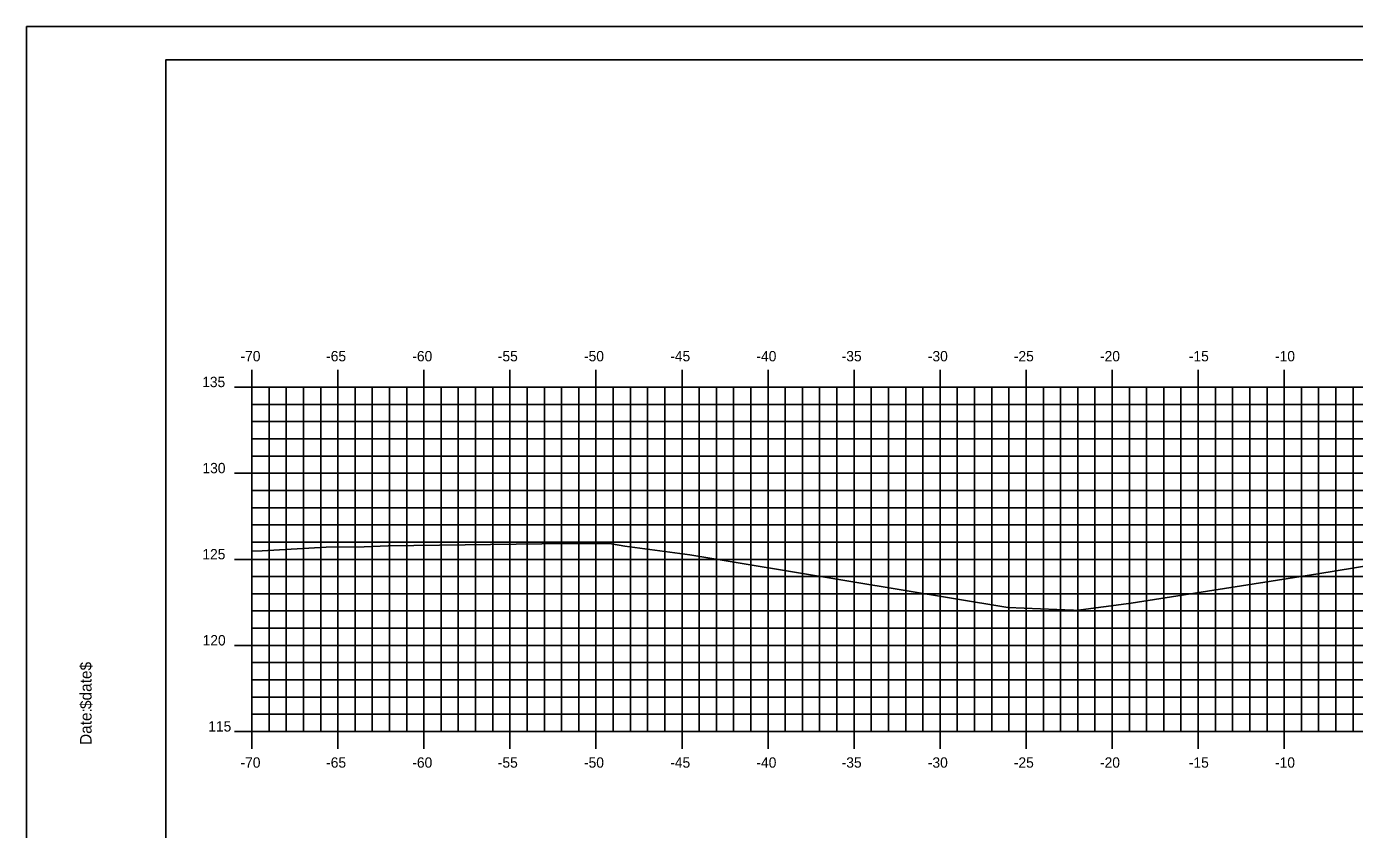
# Model space of a CAD drawing. Extents: x 851738 to 851910, y 365624 to 365734.
# Drawn here: x 851738.4 to 851815.6, y 365687.3 to 365734 of the extents above; entities that cross this region are included whole.
import ezdxf

# ---------------------------------------------------------------- set-up
doc = ezdxf.new("R2010")
doc.units = 0
for name, color, linetype in [('BORDER', 7, 'Continuous'), ('H_V ANNOTATION', 7, 'Continuous'), ('M_Roadway_Centerline', 7, 'Continuous'), ('MAJOR', 7, 'Continuous'), ('MINOR', 7, 'Continuous'), ('PLOT BOUNDARY', 7, 'Continuous'), ('S_Roadway_Centerline', 7, 'Continuous')]:
    doc.layers.add(name, color=color, linetype=linetype)

msp = doc.modelspace()

# ---------------------------------------------------------------- linework, layer by layer
at = {"layer": 'BORDER'}
msp.add_lwpolyline([(851746.522, 365627.027), (851906.522, 365627.027), (851906.522, 365732.027), (851746.522, 365732.027)], close=True, dxfattribs=at)
at = {"layer": 'MAJOR'}
for p, q in [((851751.522, 365714.029), (851751.522, 365713.027)), ((851756.522, 365714.029), (851756.522, 365713.027)), ((851761.522, 365714.029), (851761.522, 365713.027)), ((851766.522, 365714.029), (851766.522, 365713.027)), ((851771.522, 365714.029), (851771.522, 365713.027)), ((851776.522, 365714.029), (851776.522, 365713.027)), ((851781.522, 365714.029), (851781.522, 365713.027)), ((851786.522, 365714.029), (851786.522, 365713.027)), ((851791.522, 365714.029), (851791.522, 365713.027)), ((851796.522, 365714.029), (851796.522, 365713.027)), ((851801.522, 365714.029), (851801.522, 365713.027)), ((851806.522, 365714.029), (851806.522, 365713.027)), ((851811.522, 365714.029), (851811.522, 365713.027)), ((851750.52, 365713.027), (851751.522, 365713.027)), ((851751.522, 365713.027), (851891.522, 365713.027)), ((851751.522, 365693.027), (851751.522, 365713.027)), ((851751.522, 365693.027), (851751.522, 365713.027)), ((851751.522, 365713.027), (851891.522, 365713.027)), ((851756.522, 365693.027), (851756.522, 365713.027)), ((851761.522, 365693.027), (851761.522, 365713.027)), ((851766.522, 365693.027), (851766.522, 365713.027)), ((851771.522, 365693.027), (851771.522, 365713.027)), ((851776.522, 365693.027), (851776.522, 365713.027)), ((851781.522, 365693.027), (851781.522, 365713.027)), ((851786.522, 365693.027), (851786.522, 365713.027)), ((851791.522, 365693.027), (851791.522, 365713.027)), ((851796.522, 365693.027), (851796.522, 365713.027)), ((851801.522, 365693.027), (851801.522, 365713.027)), ((851806.522, 365693.027), (851806.522, 365713.027)), ((851811.522, 365693.027), (851811.522, 365713.027)), ((851750.52, 365708.027), (851751.522, 365708.027)), ((851751.522, 365708.027), (851891.522, 365708.027)), ((851750.52, 365703.027), (851751.522, 365703.027)), ((851751.522, 365703.027), (851891.522, 365703.027)), ((851750.52, 365698.027), (851751.522, 365698.027)), ((851751.522, 365698.027), (851891.522, 365698.027)), ((851750.52, 365693.027), (851751.522, 365693.027)), ((851751.522, 365693.027), (851891.522, 365693.027)), ((851751.522, 365693.027), (851891.522, 365693.027)), ((851751.522, 365692.025), (851751.522, 365693.027)), ((851756.522, 365692.025), (851756.522, 365693.027)), ((851761.522, 365692.025), (851761.522, 365693.027)), ((851766.522, 365692.025), (851766.522, 365693.027)), ((851771.522, 365692.025), (851771.522, 365693.027)), ((851776.522, 365692.025), (851776.522, 365693.027)), ((851781.522, 365692.025), (851781.522, 365693.027)), ((851786.522, 365692.025), (851786.522, 365693.027)), ((851791.522, 365692.025), (851791.522, 365693.027)), ((851796.522, 365692.025), (851796.522, 365693.027)), ((851801.522, 365692.025), (851801.522, 365693.027)), ((851806.522, 365692.025), (851806.522, 365693.027)), ((851811.522, 365692.025), (851811.522, 365693.027))]:
    msp.add_line(p, q, dxfattribs=at)
at = {"layer": 'MINOR'}
for p, q in [((851752.522, 365693.027), (851752.522, 365713.027)), ((851753.522, 365693.027), (851753.522, 365713.027)), ((851754.522, 365693.027), (851754.522, 365713.027)), ((851755.522, 365693.027), (851755.522, 365713.027)), ((851757.522, 365693.027), (851757.522, 365713.027)), ((851758.522, 365693.027), (851758.522, 365713.027)), ((851759.522, 365693.027), (851759.522, 365713.027)), ((851760.522, 365693.027), (851760.522, 365713.027)), ((851762.522, 365693.027), (851762.522, 365713.027)), ((851763.522, 365693.027), (851763.522, 365713.027)), ((851764.522, 365693.027), (851764.522, 365713.027)), ((851765.522, 365693.027), (851765.522, 365713.027)), ((851767.522, 365693.027), (851767.522, 365713.027)), ((851768.522, 365693.027), (851768.522, 365713.027)), ((851769.522, 365693.027), (851769.522, 365713.027)), ((851770.522, 365693.027), (851770.522, 365713.027)), ((851772.522, 365693.027), (851772.522, 365713.027)), ((851773.522, 365693.027), (851773.522, 365713.027)), ((851774.522, 365693.027), (851774.522, 365713.027)), ((851775.522, 365693.027), (851775.522, 365713.027)), ((851777.522, 365693.027), (851777.522, 365713.027)), ((851778.522, 365693.027), (851778.522, 365713.027)), ((851779.522, 365693.027), (851779.522, 365713.027)), ((851780.522, 365693.027), (851780.522, 365713.027)), ((851782.522, 365693.027), (851782.522, 365713.027)), ((851783.522, 365693.027), (851783.522, 365713.027)), ((851784.522, 365693.027), (851784.522, 365713.027)), ((851785.522, 365693.027), (851785.522, 365713.027)), ((851787.522, 365693.027), (851787.522, 365713.027)), ((851788.522, 365693.027), (851788.522, 365713.027)), ((851789.522, 365693.027), (851789.522, 365713.027)), ((851790.522, 365693.027), (851790.522, 365713.027)), ((851792.522, 365693.027), (851792.522, 365713.027)), ((851793.522, 365693.027), (851793.522, 365713.027)), ((851794.522, 365693.027), (851794.522, 365713.027)), ((851795.522, 365693.027), (851795.522, 365713.027)), ((851797.522, 365693.027), (851797.522, 365713.027)), ((851798.522, 365693.027), (851798.522, 365713.027)), ((851799.522, 365693.027), (851799.522, 365713.027)), ((851800.522, 365693.027), (851800.522, 365713.027)), ((851802.522, 365693.027), (851802.522, 365713.027)), ((851803.522, 365693.027), (851803.522, 365713.027)), ((851804.522, 365693.027), (851804.522, 365713.027)), ((851805.522, 365693.027), (851805.522, 365713.027)), ((851807.522, 365693.027), (851807.522, 365713.027)), ((851808.522, 365693.027), (851808.522, 365713.027)), ((851809.522, 365693.027), (851809.522, 365713.027)), ((851810.522, 365693.027), (851810.522, 365713.027)), ((851812.522, 365693.027), (851812.522, 365713.027)), ((851813.522, 365693.027), (851813.522, 365713.027)), ((851814.522, 365693.027), (851814.522, 365713.027)), ((851815.522, 365693.027), (851815.522, 365713.027)), ((851751.522, 365712.027), (851891.522, 365712.027)), ((851751.522, 365712.027), (851752.524, 365712.027)), ((851751.522, 365711.027), (851891.522, 365711.027)), ((851751.522, 365711.027), (851752.524, 365711.027)), ((851751.522, 365710.027), (851891.522, 365710.027)), ((851751.522, 365710.027), (851752.524, 365710.027)), ((851751.522, 365709.027), (851891.522, 365709.027)), ((851751.522, 365709.027), (851752.524, 365709.027)), ((851751.522, 365707.027), (851891.522, 365707.027)), ((851751.522, 365707.027), (851752.524, 365707.027)), ((851751.522, 365706.027), (851891.522, 365706.027)), ((851751.522, 365706.027), (851752.524, 365706.027)), ((851751.522, 365705.027), (851891.522, 365705.027)), ((851751.522, 365705.027), (851752.524, 365705.027)), ((851751.522, 365704.027), (851891.522, 365704.027)), ((851751.522, 365704.027), (851752.524, 365704.027)), ((851751.522, 365702.027), (851891.522, 365702.027)), ((851751.522, 365702.027), (851752.524, 365702.027)), ((851751.522, 365701.027), (851891.522, 365701.027)), ((851751.522, 365701.027), (851752.524, 365701.027)), ((851751.522, 365700.027), (851891.522, 365700.027)), ((851751.522, 365700.027), (851752.524, 365700.027)), ((851751.522, 365699.027), (851891.522, 365699.027)), ((851751.522, 365699.027), (851752.524, 365699.027)), ((851751.522, 365697.027), (851891.522, 365697.027)), ((851751.522, 365697.027), (851752.524, 365697.027)), ((851751.522, 365696.027), (851891.522, 365696.027)), ((851751.522, 365696.027), (851752.524, 365696.027)), ((851751.522, 365695.027), (851891.522, 365695.027)), ((851751.522, 365695.027), (851752.524, 365695.027)), ((851751.522, 365694.027), (851891.522, 365694.027)), ((851751.522, 365694.027), (851752.524, 365694.027))]:
    msp.add_line(p, q, dxfattribs=at)
at = {"layer": 'PLOT BOUNDARY'}
msp.add_lwpolyline([(851738.429, 365623.968), (851908.429, 365623.968), (851908.429, 365733.968), (851738.429, 365733.968)], close=True, dxfattribs=at)
at = {"layer": 'S_Roadway_Centerline'}
msp.add_lwpolyline([(851751.522, 365703.494), (851752.127, 365703.521), (851755.836, 365703.735), (851758.055, 365703.761), (851759.441, 365703.809), (851769.858, 365703.939), (851772.417, 365703.92), (851773.193, 365703.792), (851776.983, 365703.296), (851795.456, 365700.231), (851795.461, 365700.231), (851795.461, 365700.231), (851799.264, 365700.083), (851799.402, 365700.06), (851802.62, 365700.487), (851813.468, 365702.176), (851817.844, 365702.898)], dxfattribs=at)

# ---------------------------------------------------------------- texts
at = {"layer": 'BORDER'}
for s, p in [('$date$', (851742.207, 365694.332)), ('Date:', (851742.207, 365692.244))]:
    msp.add_text(s, height=0.6696, rotation=90, dxfattribs=at).set_placement(p)
at = {"layer": 'H_V ANNOTATION'}
for s, p in [('-70', (851750.864, 365714.527)), ('-65', (851755.84, 365714.527)), ('-60', (851760.848, 365714.527)), ('-55', (851765.818, 365714.527)), ('-50', (851770.826, 365714.527)), ('-45', (851775.84, 365714.527)), ('-40', (851780.848, 365714.527)), ('-35', (851785.802, 365714.527)), ('-30', (851790.81, 365714.527)), ('-25', (851795.808, 365714.527)), ('-20', (851800.816, 365714.527)), ('-15', (851805.979, 365714.527)), ('-10', (851810.987, 365714.527)), ('135', (851748.636, 365713.027)), ('130', (851748.652, 365708.027)), ('125', (851748.647, 365703.027)), ('120', (851748.663, 365698.027)), ('115', (851748.989, 365693.027)), ('-70', (851750.864, 365690.927)), ('-65', (851755.84, 365690.927)), ('-60', (851760.848, 365690.927)), ('-55', (851765.818, 365690.927)), ('-50', (851770.826, 365690.927)), ('-45', (851775.84, 365690.927)), ('-40', (851780.848, 365690.927)), ('-35', (851785.802, 365690.927)), ('-30', (851790.81, 365690.927)), ('-25', (851795.808, 365690.927)), ('-20', (851800.816, 365690.927)), ('-15', (851805.979, 365690.927)), ('-10', (851810.987, 365690.927))]:
    msp.add_text(s, height=0.6, dxfattribs=at).set_placement(p)
at = {"layer": 'M_Roadway_Centerline'}
for s, p in [('C', (851755.83, 365703.735)), ('L', (851755.836, 365703.728))]:
    msp.add_text(s, height=0.0146, dxfattribs=at).set_placement(p)
at = {"layer": 'MAJOR'}
msp.add_text('-', height=0.006, dxfattribs=at).set_placement((851751.518, 365693.027))

doc.saveas('drawing.dxf')
